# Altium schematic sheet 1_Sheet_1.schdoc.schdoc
size 482 x 210 mm
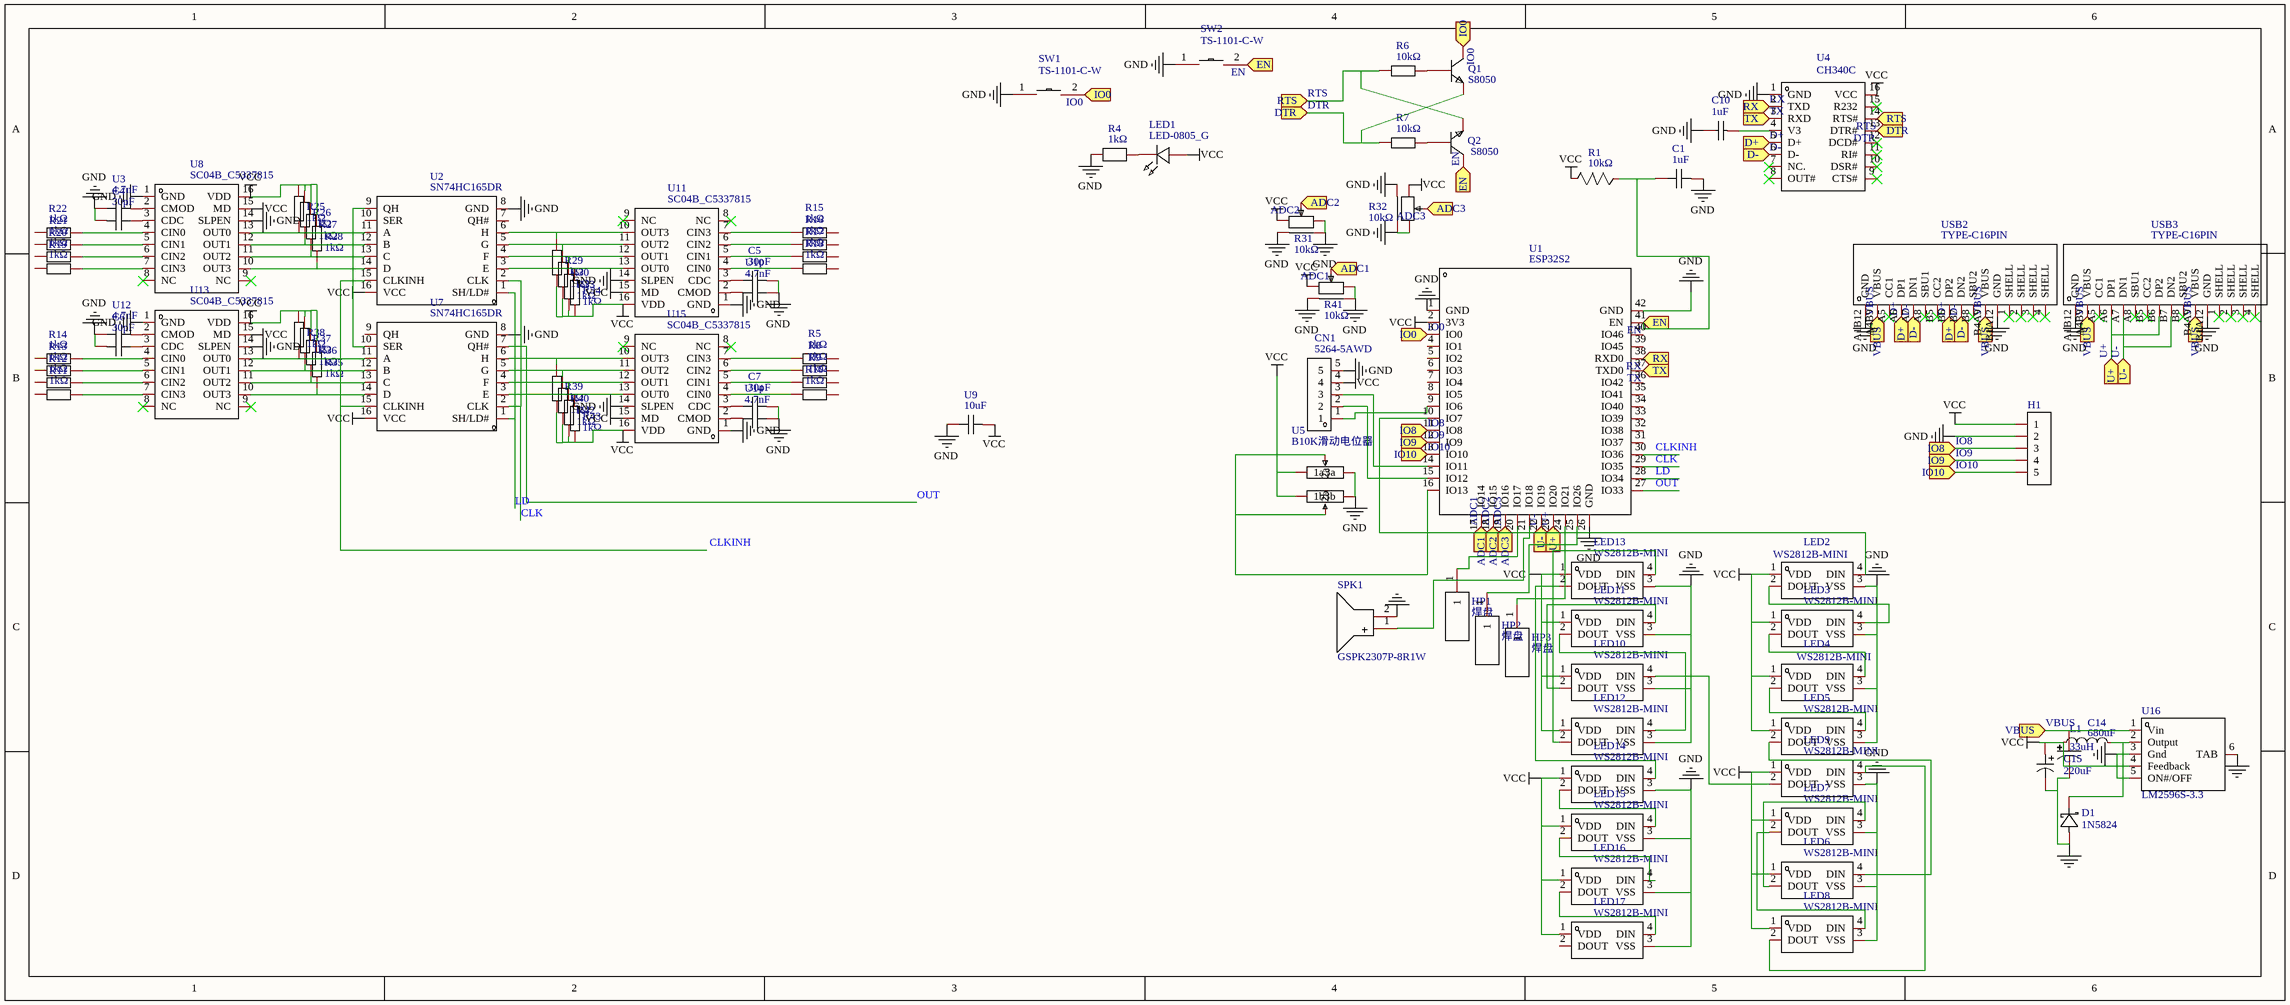
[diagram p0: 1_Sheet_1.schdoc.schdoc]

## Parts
C1  1uF  [C0603]
C4  30pF  [C0603]
C5  30pF  [C0603]
C6  30pF  [C0603]
C7  30pF  [C0603]
C10  1uF  [C0805]
C14  680uF  [CAP-TH_BD6.3-P2.50-D1.0-FD]
C15  220uF  [CAP-TH_BD8.0-P3.50-D0.6-FD-2]
CN1  5264-5AWD  [CONN-TH_5P-P2.50_5264-5AWD]
D1  1N5824  [DO-27_BD5.3-L8.4-P12.40-D1.3-RD]
H1  HDR-F_2.54_1x5P  [HDR-TH_5P-P2.54-V-F]  (value not drawn)
HP1  焊盘  [焊盘]
HP2  焊盘  [焊盘]
HP3  焊盘  [焊盘]
L1  33uH  [IND-SMD_L7.0-W6.6_FXL0630]
LED1  LED-0805_G  [LED0805_GREEN]
LED2  WS2812B-MINI  [LED-SMD_4P-L3.5-W3.5-TL_WS2812B]
LED3  WS2812B-MINI  [LED-SMD_4P-L3.5-W3.5-TL_WS2812B]
LED4  WS2812B-MINI  [LED-SMD_4P-L3.5-W3.5-TL_WS2812B]
LED5  WS2812B-MINI  [LED-SMD_4P-L3.5-W3.5-TL_WS2812B]
LED6  WS2812B-MINI  [LED-SMD_4P-L3.5-W3.5-TL_WS2812B]
LED7  WS2812B-MINI  [LED-SMD_4P-L3.5-W3.5-TL_WS2812B]
LED8  WS2812B-MINI  [LED-SMD_4P-L3.5-W3.5-TL_WS2812B]
LED9  WS2812B-MINI  [LED-SMD_4P-L3.5-W3.5-TL_WS2812B]
LED10  WS2812B-MINI  [LED-SMD_4P-L3.5-W3.5-TL_WS2812B]
LED11  WS2812B-MINI  [LED-SMD_4P-L3.5-W3.5-TL_WS2812B]
LED12  WS2812B-MINI  [LED-SMD_4P-L3.5-W3.5-TL_WS2812B]
LED13  WS2812B-MINI  [LED-SMD_4P-L3.5-W3.5-TL_WS2812B]
LED14  WS2812B-MINI  [LED-SMD_4P-L3.5-W3.5-TL_WS2812B]
LED15  WS2812B-MINI  [LED-SMD_4P-L3.5-W3.5-TL_WS2812B]
LED16  WS2812B-MINI  [LED-SMD_4P-L3.5-W3.5-TL_WS2812B]
LED17  WS2812B-MINI  [LED-SMD_4P-L3.5-W3.5-TL_WS2812B]
Q1  S8050  [SOT-23-3_L2.9-W1.3-P1.90-LS2.4-BR]
Q2  S8050  [SOT-23-3_L2.9-W1.3-P1.90-LS2.4-BR]
R1  10kΩ  [R0603]
R4  1kΩ  [R0805]
R5  1kΩ  [R0603]
R6  10kΩ  [R0805]
R7  10kΩ  [R0805]
R8  1kΩ  [R0603]
R9  1kΩ  [R0603]
R10  1kΩ  [R0603]
R11  1kΩ  [R0603]
R12  1kΩ  [R0603]
R13  1kΩ  [R0603]
R14  1kΩ  [R0603]
R15  1kΩ  [R0603]
R16  1kΩ  [R0603]
R17  1kΩ  [R0603]
R18  1kΩ  [R0603]
R19  1kΩ  [R0603]
R20  1kΩ  [R0603]
R21  1kΩ  [R0603]
R22  1kΩ  [R0603]
R25  1kΩ  [R0603]
R26  1kΩ  [R0603]
R27  1kΩ  [R0603]
R28  1kΩ  [R0603]
R29  1kΩ  [R0603]
R30  1kΩ  [R0603]
R31  10kΩ  [RES-ADJ-TH_RK09K1130AJ3]
R32  10kΩ  [RES-ADJ-TH_RK09K1130AJ3]
R33  1kΩ  [R0603]
R34  1kΩ  [R0603]
R35  1kΩ  [R0603]
R36  1kΩ  [R0603]
R37  1kΩ  [R0603]
R38  1kΩ  [R0603]
R39  1kΩ  [R0603]
R40  1kΩ  [R0603]
R41  10kΩ  [RES-ADJ-TH_RK09K1130AJ3]
R42  1kΩ  [R0603]
R43  1kΩ  [R0603]
SPK1  GSPK2307P-8R1W  [SPK-TH_BD23.0-P10.00-D0.8-L-RD]
SW1  TS-1101-C-W  [SW-SMD_L6.0-W3.3-LS8.0]
SW2  TS-1101-C-W  [SW-SMD_L6.0-W3.3-LS8.0]
U1  ESP32S2  [ESP32S2]
U2  SN74HC165DR  [SOP-16_L10.0-W3.9-P1.27-LS6.0-BL]
U3  4.7nF  [C0603]
U4  CH340C  [SOP-16_L10.0-W3.9-P1.27-LS6.0-BL]
U5  B10K滑动电位器  [B10K]
U7  SN74HC165DR  [SOP-16_L10.0-W3.9-P1.27-LS6.0-BL]
U8  SC04B_C5337815  [SOP-16_L10.0-W3.9-P1.27-LS6.0-BL]
U9  10uF  [C1206]
U10  4.7nF  [C0603]
U11  SC04B_C5337815  [SOP-16_L10.0-W3.9-P1.27-LS6.0-BL]
U12  4.7nF  [C0603]
U13  SC04B_C5337815  [SOP-16_L10.0-W3.9-P1.27-LS6.0-BL]
U14  4.7nF  [C0603]
U15  SC04B_C5337815  [SOP-16_L10.0-W3.9-P1.27-LS6.0-BL]
U16  LM2596S-3.3  [TO-263-5_L10.0-W8.4-P1.70-LS15.3-BR]
USB2  TYPE-C16PIN  [USB-C-SMD_TYPE-C16PIN]
USB3  TYPE-C16PIN  [USB-C-SMD_TYPE-C16PIN]

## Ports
ADC1 (in), ADC2 (in), ADC3 (in), D+ (in), D- (in), DTR (in), EN (in), IO0 (in), IO8 (in), IO9 (in), IO10 (in), RTS (in), RX (in), TX (in), U+ (in), U- (in), VBUS (in)

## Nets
GND: C1.2 C4.2 C5.2 C6.2 C7.2 C10.2 C14.2 C15.2 CN1.5 D1.2(A) H1.2 LED2.3(VSS) LED3.3(VSS) LED4.3(VSS) LED5.3(VSS) LED6.3(VSS) LED7.3(VSS) LED8.3(VSS) LED9.3(VSS) LED10.3(VSS) LED11.3(VSS) LED12.3(VSS) LED13.3(VSS) LED14.3(VSS) LED15.3(VSS) LED16.3(VSS) LED17.3(VSS) R4.1 R31.1 R31.4 R31.5 R32.1 R32.4 R32.5 R41.1 R41.4 R41.5 SPK1.2(-) SW1.1 SW2.1 U1.1(GND) U1.26(GND) U1.42(GND) U2.8(GND) U3.1 U4.1(GND) U5.3a U5.3b U7.8(GND) U8.1(GND) U8.14(SLPEN) U9.1 U10.1 U11.1(GND) U11.14(SLPEN) U12.1 U13.1(GND) U13.14(SLPEN) U14.1 U15.1(GND) U15.14(SLPEN) U16.3(Gnd) U16.5(ON#/OFF) U16.6(TAB) USB2.A1B12(GND) USB2.B1A12(GND) USB3.A1B12(GND) USB3.B1A12(GND)
VCC: C15.1 CN1.4 H1.1 L1.1 LED1.1 LED2.1(VDD) LED3.1(VDD) LED4.1(VDD) LED5.1(VDD) LED6.1(VDD) LED7.1(VDD) LED8.1(VDD) LED9.1(VDD) LED10.1(VDD) LED11.1(VDD) LED12.1(VDD) LED13.1(VDD) LED14.1(VDD) LED15.1(VDD) LED16.1(VDD) LED17.1(VDD) R1.1 R25.1 R26.1 R27.1 R28.1 R29.1 R30.1 R31.3 R32.3 R33.1 R34.1 R35.1 R36.1 R37.1 R38.1 R39.1 R40.1 R41.3 R42.1 R43.1 U1.2(3V3) U2.16(VCC) U4.16(VCC) U5.1a U5.1b U7.16(VCC) U8.15(MD) U8.16(VDD) U9.2 U11.15(MD) U11.16(VDD) U13.15(MD) U13.16(VDD) U15.15(MD) U15.16(VDD) U16.4(Feedback)
ADC1: R41.2 U1.17(IO14) ; port ADC1
ADC2: R31.2 U1.18(IO15) ; port ADC2
ADC3: R32.2 U1.19(IO16) ; port ADC3
CLK: U1.29(IO35) U2.2(CLK) U7.2(CLK)
CLKINH: U1.30(IO36)
D+: U4.5(D+) USB2.A6(DP1) USB2.B6(DP2) ; port D+
D-: U4.6(D-) USB2.A7(DN1) USB2.B7(DN2) ; port D-
DTR: Q1.2(E) R7.1 U4.13(DTR#) ; port DTR
EN: C1.1 Q2.3(C) R1.2 SW2.2 U1.41(EN) ; port EN
IO0: Q1.3(C) SW1.2 U1.3(IO0) ; port IO0
IO8: H1.3 U1.11(IO8) ; port IO8
IO9: H1.4 U1.12(IO9) ; port IO9
IO10: H1.5 U1.13(IO10) ; port IO10
LD: U1.28(IO34) U2.1(SH/LD#) U7.1(SH/LD#)
OUT: U1.27(IO33) U7.7(QH#)
RTS: Q2.2(E) R6.1 U4.14(RTS#) ; port RTS
RX: U1.38(RXD0) U4.2(TXD) ; port RX
TX: U1.37(TXD0) U4.3(RXD) ; port TX
U+: LED12.2(DOUT) LED13.4(DIN) U1.23(IO20) USB3.A6(DP1) USB3.B6(DP2) ; port U+
U-: U1.22(IO19) USB3.A7(DN1) USB3.B7(DN2) ; port U-
VBUS: C14.1 U16.1(Vin) USB2.A4B9(VBUS) USB2.B4A9(VBUS) USB3.A4B9(VBUS) USB3.B4A9(VBUS) ; port VBUS
NetC4_1: C4.1 U8.3(CDC)
NetC5_1: C5.1 U11.3(CDC)
NetC6_1: C6.1 U13.3(CDC)
NetC7_1: C7.1 U15.3(CDC)
NetC10_1: C10.1 U4.4(V3)
NetCN1_1: CN1.1 U1.9(IO6)
NetCN1_2: CN1.2 U1.15(IO12)
NetCN1_3: CN1.3 U1.14(IO11)
NetD1_1: D1.1(K) L1.2 U16.2(Output)
NetHP1_1: HP1.1 U1.20(IO17)
NetHP2_1: HP2.1 U1.25(IO26)
NetHP3_1: HP3.1 U1.24(IO21)
NetLED1_2: LED1.2 R4.2
NetLED2_2: LED2.2(DOUT) LED3.4(DIN)
NetLED2_4: LED2.4(DIN) U1.10(IO7)
NetLED3_2: LED3.2(DOUT) LED4.4(DIN)
NetLED4_2: LED4.2(DOUT) LED5.4(DIN)
NetLED5_2: LED5.2(DOUT) LED6.4(DIN)
NetLED6_2: LED6.2(DOUT) LED7.4(DIN)
NetLED7_2: LED7.2(DOUT) LED8.4(DIN)
NetLED8_2: LED8.2(DOUT) LED9.4(DIN)
NetLED9_2: LED9.2(DOUT) LED10.4(DIN)
NetLED10_2: LED10.2(DOUT) LED11.4(DIN)
NetLED11_2: LED11.2(DOUT) LED12.4(DIN)
NetLED13_2: LED13.2(DOUT) LED14.4(DIN)
NetLED14_2: LED14.2(DOUT) LED15.4(DIN)
NetLED15_2: LED15.2(DOUT) LED16.4(DIN)
NetLED16_2: LED16.2(DOUT) LED17.4(DIN)
NetQ1_1: Q1.1(B) R6.2
NetQ2_1: Q2.1(B) R7.2
NetR5_1: R5.1 U15.7(CIN3)
NetR8_1: R8.1 U15.6(CIN2)
NetR9_1: R9.1 U15.5(CIN1)
NetR10_1: R10.1 U15.4(CIN0)
NetR11_1: R11.1 U13.7(CIN3)
NetR12_1: R12.1 U13.6(CIN2)
NetR13_1: R13.1 U13.5(CIN1)
NetR14_1: R14.1 U13.4(CIN0)
NetR15_1: R15.1 U11.7(CIN3)
NetR16_1: R16.1 U11.6(CIN2)
NetR17_1: R17.1 U11.5(CIN1)
NetR18_1: R18.1 U11.4(CIN0)
NetR19_1: R19.1 U8.7(CIN3)
NetR20_1: R20.1 U8.6(CIN2)
NetR21_1: R21.1 U8.5(CIN1)
NetR22_1: R22.1 U8.4(CIN0)
NetR25_2: R25.2 U2.11(A) U8.13(OUT0)
NetR26_2: R26.2 U2.12(B) U8.12(OUT1)
NetR27_2: R27.2 U2.13(C) U8.11(OUT2)
NetR28_2: R28.2 U2.14(D) U8.10(OUT3)
NetR29_2: R29.2 U2.6(H) U11.10(OUT3)
NetR30_2: R30.2 U2.5(G) U11.11(OUT2)
NetR33_2: R33.2 U2.4(F) U11.12(OUT1)
NetR34_2: R34.2 U2.3(E) U11.13(OUT0)
NetR35_2: R35.2 U7.14(D) U13.10(OUT3)
NetR36_2: R36.2 U7.13(C) U13.11(OUT2)
NetR37_2: R37.2 U7.12(B) U13.12(OUT1)
NetR38_2: R38.2 U7.11(A) U13.13(OUT0)
NetR39_2: R39.2 U7.6(H) U15.10(OUT3)
NetR40_2: R40.2 U7.5(G) U15.11(OUT2)
NetR42_2: R42.2 U7.4(F) U15.12(OUT1)
NetR43_2: R43.2 U7.3(E) U15.13(OUT0)
NetSPK1_1: SPK1.1(+) U1.21(IO18)
NetU1_16: U1.16(IO13) U5.2a U5.2b
NetU2_9: U2.9(QH) U7.10(SER)
NetU2_15: U2.15(CLKINH) U7.15(CLKINH)
NetU3_2: U3.2 U8.2(CMOD)
NetU10_2: U10.2 U11.2(CMOD)
NetU12_2: U12.2 U13.2(CMOD)
NetU14_2: U14.2 U15.2(CMOD)

Not connected (* = marked no-connect by the designer): LED17 2(DOUT); R5 2; R8 2; R9 2; R10 2; R11 2; R12 2; R13 2; R14 2; R15 2; R16 2; R17 2; R18 2; R19 2; R20 2; R21 2; R22 2; U1 4(IO1) 5(IO2) 6(IO3) 7(IO4) 8(IO5) 31(IO37) 32(IO38) 33(IO39) 34(IO40) 35(IO41) 36(IO42) 39(IO45) 40(IO46); U2 7(QH#) 10(SER); U4 7(NC.)* 8(OUT#)* 9(CTS#)* 10(DSR#)* 11(RI#)* 12(DCD#)* 15(R232)*; U7 9(QH); U8 8(NC)* 9(NC)*; U11 8(NC)* 9(NC)*; U13 8(NC)* 9(NC)*; U15 8(NC)* 9(NC)*; USB2 1(SHELL)* 2(SHELL)* 3(SHELL)* 4(SHELL)* A5(CC1)* A8(SBU1)* B5(CC2)* B8(SBU2)*; USB3 1(SHELL)* 2(SHELL)* 3(SHELL)* 4(SHELL)* A5(CC1)* A8(SBU1)* B5(CC2)* B8(SBU2)*

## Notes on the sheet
- Labels drawn without touching a wire or pin: CLKINH

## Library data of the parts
C1 = CL10A105KB8NNNC: Manufacturer: SAMSUNG(三星); Symbol: 1u; Add into BOM: yes; Tolerance: ±10%; Voltage Rated: 50V; Temperature Coefficient: X5R; Description: 容值:1uF;精度:±10%;额定电压:50V;材质(温度系数):X5R;
C4-C7 = 30pF: Manufacturer: CCTC(三环); Manufacturer Part: TCC0603COG300J500CT; Add into BOM: yes
C10 = 1uF: Manufacturer: muRata(村田); Manufacturer Part: GRM21BR61E226ME44L; Add into BOM: yes
C14 = SHW680UF10V6.3X11: Manufacturer: KNSCHA(科尼盛); Add into BOM: yes; Tolerance: ±20%; Rated Voltage: 10V; Ripple Current: 980mA@100kHz; Equivalent Series Resistance(ESR): 50mΩ@300kHz; φD: 6.3mm; L: 11mm; Lifetime @ Temp: 10000hrs@105℃; Description: 容值:680uF;精度:±20%;额定电压:10V;纹波电流:980mA@100kHz;等效串联电阻:50mΩ@300kHz;
C15 = KNH2220UF35V149EC0049: Manufacturer: KNSCHA(科尼盛); Add into BOM: yes; Tolerance: ±20%; Rated Voltage: 35V; Ripple Current: 1.7A@100kHz; Equivalent Series Resistance(ESR): 40mΩ@100kHz; φD: 8mm; L: 9mm; Lifetime @ Temp: 2000hrs@105℃; Description: 容值:220uF;精度:±20%;额定电压:35V;纹波电流:1.7A@100kHz;等效串联电阻:40mΩ@100kHz;
CN1 = 5264-5AWD: Manufacturer: BOOMELE(博穆精密); Manufacturer Part: 5264-5AWD米色; Add into BOM: yes
D1 = 1N5824_C7503125: Manufacturer: FUXINSEMI(富芯森美); Add into BOM: yes; Diode Configuration: 独立式; Forward Voltage (Vf@If): 550mV@5A; Reverse Voltage (Vr): 30V; Average Rectified Current (Io): 5A; Reverse Leakage Current (Ir): 500uA@30V; Peak forward surge current: 150A; Description: 二极管配置:独立式;正向压降(Vf):550mV@5A;直流反向耐压(Vr):30V;平均整流电流(Io):5A;
H1 = HDR-F_2.54_1x5P: Manufacturer: BOOMELE(博穆精密); Manufacturer Part: 2.54-1*5P母; Symbol: Header-Female-2.54_1x5; Convert to PCB: yes
HP1-HP3 = 焊盘: Manufacturer: .....; Add into BOM: yes; Check: false
L1 = FXL0630-330-M: Manufacturer: cjiang(长江微电); Add into BOM: yes; Tolerance: ±20%; Rated Current: 2A; Saturation Current (Isat): 2.5A; DC Resistance (DCR): 310mΩ; Type: 一体成型电感; Description: 电感值:33uH;精度:±20%;额定电流:2A;饱和电流(Isat):2.5A;类型:一体成型电感;
LED1 = LED-0805_G: Manufacturer: 国星光电; Manufacturer Part: NCD0805G1; Add into BOM: yes
LED2-LED17 = WS2812B-MINI: Manufacturer: worldsemi; Manufacturer Part: WS2812B-MINI-V3/W; Add into BOM: yes
Q1 Q2 = S8050: Manufacturer: Yenji; Add into BOM: yes
R1 = 0603WAF1002T5E: Manufacturer: UNI-ROYAL(厚声); Symbol: 10k; Add into BOM: yes; Tolerance: ±1%; Power(Watts): 100mW; Overload Voltage (Max): 75V; Temperature Coefficient: ±100ppm/℃; Description: 电阻类型:厚膜电阻;阻值:10kΩ;精度:±1%;功率:100mW;最大工作电压:75V;温度系数:±100ppm/℃;
R4 = 1kΩ: Manufacturer: UNI-ROYAL(厚声); Manufacturer Part: 0805W8D1001T5E; Add into BOM: yes
R5 R8-R22 R25-R30 R33-R40 R42 R43 = 1kΩ: Manufacturer: PANASONIC(松下); Manufacturer Part: ERJ3RBD1001V; Add into BOM: yes
R6 R7 = 10kΩ: Manufacturer: UNI-ROYAL(厚声); Manufacturer Part: 0805W8F1002T5E; Add into BOM: yes
R31 R32 R41 = 10kΩ: Manufacturer: ALPSALPINE(阿尔卑斯阿尔派); Manufacturer Part: RK09K1130AP5; Add into BOM: yes
SPK1 = GSPK2307P-8R1W: Manufacturer: INGHAi(赢海); Add into BOM: yes
SW1 SW2 = TS-1101-C-W: Manufacturer: XKB Connectivity(中国星坤); Add into BOM: yes
U1 = ESP32S2: Manufacturer: ESPRESSIF(乐鑫); Manufacturer Part: ESP32-S2-WROVER-I-N8R2; Add into BOM: yes
U2 U7 = SN74HC165DR: Manufacturer: TI(德州仪器); Add into BOM: yes
U3 U10 U12 U14 = 4.7nF: Manufacturer: TDK; Manufacturer Part: C1608JB2A472M080AA; Add into BOM: yes
U4 = CH340C: Manufacturer: WCH(南京沁恒); Add into BOM: yes
U5 = B10K滑动电位器: Add into BOM: yes; Check: false
U8 U11 U13 U15 = SC04B_C5337815: Manufacturer: icman(晶尊微); Manufacturer Part: SC04B; Add into BOM: yes
U9 = 10uF: Manufacturer: SAMWHA(三和); Manufacturer Part: CS3216Y5V106Z350NRI; Add into BOM: yes
U16 = LM2596S-3.3: Manufacturer: UMW(友台半导体); Add into BOM: yes; Function: 降压型; Output Type: 固定; Input Voltage: 40V; Output Voltage: 3.3V; Output Current (Max): 3A; Switching Frequency: 150kHz; Synchronous Rectification: 否; Number of Outputs: 1; Topology: 降压式; Switch tube (built-in/external): 内置; Description: 功能类型:降压型;输出类型:固定;输入电压:40V;输出电压:3.3V;输出电流(最大值):3A;
USB2 USB3 = TYPE-C16PIN: Manufacturer: SHOU HAN(首韩); Add into BOM: yes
